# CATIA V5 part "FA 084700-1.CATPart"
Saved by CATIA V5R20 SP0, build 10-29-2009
Part number: FA 084700-1
Revision: ANY
Definition: UNKNOWN
Nomenclature: FA 084700-1
Source: Unknown
Bounding box of the stored display mesh (mm): x -2.853 to 2.853, y 0.2 to 2.5, z -3 to 3
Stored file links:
  C:\Users\Utente\Desktop\IO LAVORO\3D X SITO CF\CUMSA\3D files FA\FA 0847SF\FA 084700-1.CATPart

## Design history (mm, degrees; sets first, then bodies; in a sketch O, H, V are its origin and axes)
Body1 "Cortar-Extruir1" (main body)
  Solid1: solid without history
